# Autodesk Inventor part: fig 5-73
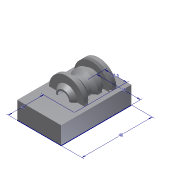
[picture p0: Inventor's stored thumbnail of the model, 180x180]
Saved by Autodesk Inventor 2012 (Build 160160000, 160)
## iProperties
Created: 2010-02
Part Number: fig 5-73
Document SubType Name: Modeling
Designer: CADSoft
Density: 1 g/cm^3
Material: Default
Author: CADSoft
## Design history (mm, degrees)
sketch "Sketch1"
  geometry: L1 (-12.5, 20)-(12.5, 20); L2 (12.5, 20)-(12.5, -20); L3 (12.5, -20)-(-12.5, -20); L4 (-12.5, -20)-(-12.5, 20); 1 further point
  constraints: 8 end point, 2 horizontal, 2 vertical
  dimensions: "d0" = 25 distance of L1.start L1.end; "d1" = 40 distance of L1.end L2.end; "d2" = 20 distance from line of L3 point (0, 0); "d3" = 12.5 distance from line of L4 point (0, 0)
extrude "Extrusion1" new body sketch "Sketch1" distance "d4" = 10; taper "d5" = 0 deg
sketch "Sketch2"
  geometry: L1 (-0.054, -20.11)-(-0.054, 21.401); L2 (3.173, 13.981)-(10.055, 13.981); L3 (10.055, 13.981)-(10.055, 11.83); L4 (10.055, 11.83)-(8.012, 10.969); L5 (8.012, 10.969)-(10.055, 10.001); L6 (10.055, 10.001)-(6.614, 10.001); L7 (6.614, 10.001)-(6.614, 7.851); L8 (6.614, 7.851)-(8.012, 7.851); L9 (8.012, 7.851)-(8.012, 5.7); L10 (8.012, 5.7)-(5.996, 4.073); L11 (5.996, 4.073)-(5.996, 1.828); L12 (5.996, 1.828)-(8.012, -0.069); L13 (8.012, -0.069)-(8.012, -2.151); L14 (8.012, -2.151)-(10.055, -2.151); L15 (10.055, -2.151)-(10.055, -4.194); L16 (10.055, -4.194)-(5.996, -4.194); L17 (5.996, -4.194)-(4.171, -6.134); L18 (4.171, -6.134)-(3.173, -6.134); L19 (3.173, -6.134)-(3.173, 13.981)
  constraints: 38 end point
revolve "Revolution1" sketch "Sketch2" stored, may be unused: angle "d6" = 180 deg
body "Solid1"
